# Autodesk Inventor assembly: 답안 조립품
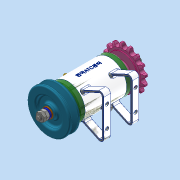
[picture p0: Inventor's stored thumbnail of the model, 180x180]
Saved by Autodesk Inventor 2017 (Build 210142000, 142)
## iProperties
Part Number: 답안 조립품
Material: 일반
Document SubType Name: Assembly
Designer: Administrator
Author: Administrator
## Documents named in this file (16)
- C:\Users\Administrator\Desktop\711206V1031\답안 조립품.iam
- C:\Users\Administrator\Desktop\711206V1031\V벨트풀리.ipt
- C:\Users\Administrator\Desktop\711206V1031\너트 M8.ipt
- C:\Users\Administrator\Desktop\711206V1031\니플 M6 x 0.75.ipt
- C:\Users\Administrator\Desktop\711206V1031\베어링 6002.ipt
- C:\Users\Administrator\Desktop\711206V1031\본체.ipt
- C:\Users\Administrator\Desktop\711206V1031\볼트 M4 x 12.ipt
- C:\Users\Administrator\Desktop\711206V1031\볼트 M6 x 8.ipt
- C:\Users\Administrator\Desktop\711206V1031\스프로킷.ipt
- C:\Users\Administrator\Desktop\711206V1031\스프링와셔 8.ipt
- C:\Users\Administrator\Desktop\711206V1031\오일 실 15 x 25 x 7.ipt
- C:\Users\Administrator\Desktop\711206V1031\와셔 6 x 11.5.ipt
- C:\Users\Administrator\Desktop\711206V1031\와셔 8 x 17.ipt
- C:\Users\Administrator\Desktop\711206V1031\축.ipt
- C:\Users\Administrator\Desktop\711206V1031\커버.ipt
- C:\Users\Administrator\Desktop\711206V1031\키 3 x 3.ipt
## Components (11 placed, 3 different names)
1. V벨트풀리:1
2. KS B 2023 6002 - 15 x 32 x 9:1
3. KS B 2023 6002 - 15 x 32 x 9:2
4. ISO 4762 M4 x 12:1
5. ISO 4762 M4 x 12:9
6. ISO 4762 M4 x 12:10
7. ISO 4762 M4 x 12:11
8. ISO 4762 M4 x 12:8
9. ISO 4762 M4 x 12:12
10. ISO 4762 M4 x 12:13
11. ISO 4762 M4 x 12:14
